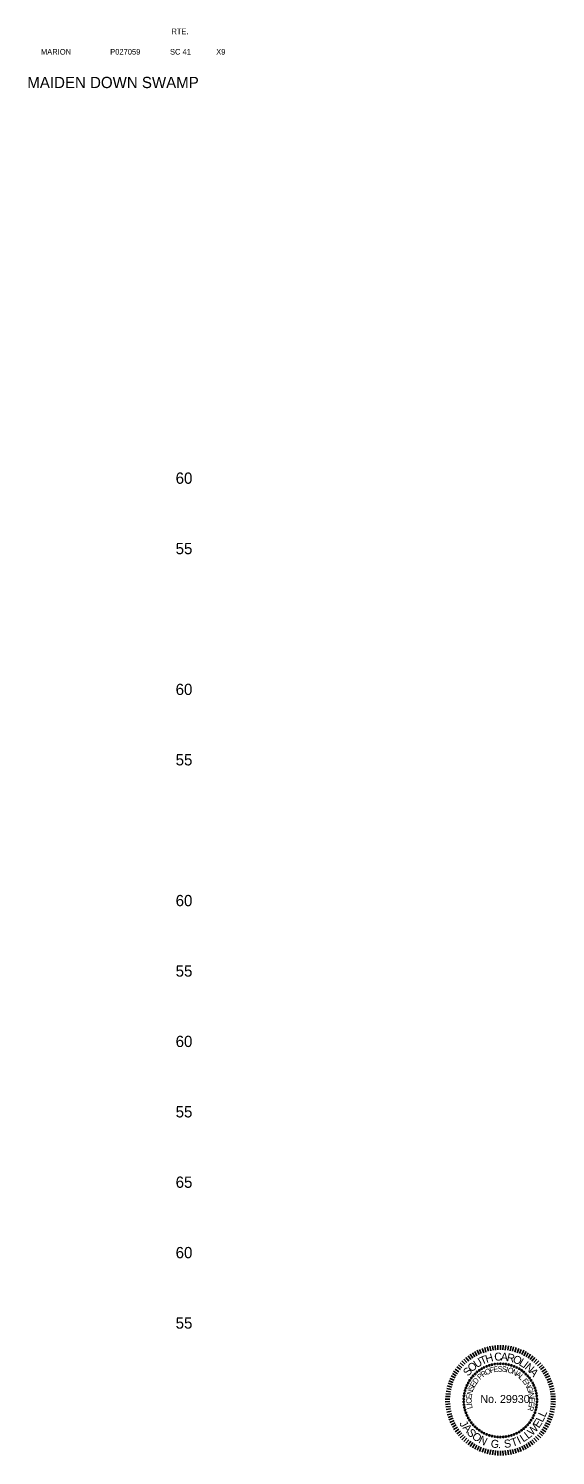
# Model space of a CAD drawing. Extents: x 1001 to 1184, y 1001 to 1447.
# Drawn here: x 1146.5 to 1183.9, y 1346 to 1447.3 of the extents above; entities that cross this region are included whole.
import ezdxf

# ---------------------------------------------------------------- set-up
doc = ezdxf.new("R2010")
doc.units = 0
for name, color, linetype in [('RD_HC_Cl', 7, 'Continuous'), ('RD_SHT_TX', 7, 'Continuous'), ('RD_TX_PEShield', 7, 'Continuous'), ('RD_XS_TX_Elev_EX', 7, 'Continuous')]:
    doc.layers.add(name, color=color, linetype=linetype)

# ---------------------------------------------------------------- blocks, each defined once
blk = doc.blocks.new('STILLWELL')
at = {"layer": 'RD_TX_PEShield'}
for p, q in [((-21.1, 28.1), (-23, 30.7)), ((-19.7, 29.1), (-21.5, 31.8)), ((-18.2, 30), (-19.9, 32.8)), ((-16.7, 30.8), (-18.2, 33.7)), ((-15.1, 31.6), (-16.5, 34.6)), ((-13.6, 32.3), (-14.8, 35.3)), ((-11.9, 32.9), (-13, 36)), ((-10.3, 33.4), (-11.2, 36.6)), ((-8.6, 33.9), (-9.4, 37.1)), ((-6.9, 34.3), (-7.5, 37.5)), ((-5.2, 34.6), (-5.7, 37.8)), ((-3.5, 34.8), (-3.8, 38)), ((-1.8, 34.9), (-1.9, 38.2)), ((0, 34.9), (0, 38.2)), ((1.7, 34.9), (1.9, 38.2)), ((3.4, 34.8), (3.7, 38)), ((5.2, 34.6), (5.6, 37.8)), ((6.9, 34.3), (7.5, 37.5)), ((8.6, 33.9), (9.3, 37.1)), ((10.2, 33.4), (11.2, 36.6)), ((11.9, 32.9), (13, 36)), ((13.5, 32.3), (14.7, 35.3)), ((15.1, 31.6), (16.5, 34.6)), ((16.6, 30.8), (18.2, 33.7)), ((18.2, 30), (19.8, 32.8)), ((19.6, 29.1), (21.4, 31.8)), ((21.1, 28.1), (23, 30.7)), ((-29.5, 19.4), (-32.2, 21.3)), ((-28.5, 20.9), (-31.1, 22.8)), ((-27.4, 22.2), (-29.9, 24.3)), ((-26.3, 23.5), (-28.7, 25.7)), ((-25.1, 24.7), (-27.4, 27.1)), ((-23.8, 25.9), (-26, 28.4)), ((-22.5, 27), (-24.5, 29.6)), ((22.4, 27), (24.5, 29.6)), ((23.8, 25.9), (25.9, 28.4)), ((25, 24.7), (27.3, 27.1)), ((26.2, 23.5), (28.6, 25.7)), ((27.4, 22.2), (29.9, 24.3)), ((28.5, 20.9), (31.1, 22.8)), ((29.5, 19.4), (32.2, 21.3)), ((-34.1, 10.2), (-37.2, 11.2)), ((-33.6, 11.8), (-36.6, 12.9)), ((-32.9, 13.4), (-35.9, 14.7)), ((-32.2, 15), (-35.1, 16.4)), ((-31.4, 16.5), (-34.2, 18.1)), ((-30.5, 18), (-33.3, 19.7)), ((30.4, 18), (33.2, 19.7)), ((31.3, 16.5), (34.2, 18.1)), ((32.1, 15), (35.1, 16.4)), ((32.9, 13.4), (35.9, 14.7)), ((33.5, 11.8), (36.6, 12.9)), ((34.1, 10.2), (37.2, 11.2)), ((-35.9, -0.1), (-39.2, 0)), ((-35.8, 1.7), (-39.1, 1.9)), ((-35.6, 3.4), (-38.9, 3.8)), ((-35.4, 5.1), (-38.6, 5.7)), ((-35.1, 6.8), (-38.2, 7.5)), ((-34.6, 8.5), (-37.8, 9.4)), ((34.6, 8.5), (37.7, 9.4)), ((35, 6.8), (38.2, 7.5)), ((35.3, 5.1), (38.5, 5.7)), ((35.6, 3.4), (38.8, 3.8)), ((35.7, 1.7), (39, 1.9)), ((35.8, -0.1), (39.1, 0)), ((-35.9, -1.8), (-39.2, -1.9)), ((-35.8, -3.5), (-39.1, -3.8)), ((-35.6, -5.3), (-38.9, -5.6)), ((-35.4, -7), (-38.6, -7.5)), ((-35.1, -8.7), (-38.2, -9.4)), ((35, -8.7), (38.2, -9.4)), ((35.3, -7), (38.5, -7.5)), ((35.6, -5.3), (38.8, -5.6)), ((35.7, -3.5), (39, -3.8)), ((35.8, -1.8), (39.1, -1.9)), ((-34.6, -10.4), (-37.8, -11.2)), ((-34.1, -12), (-37.2, -13)), ((-33.6, -13.6), (-36.6, -14.8)), ((-32.9, -15.3), (-35.9, -16.6)), ((-32.2, -16.8), (-35.1, -18.3)), ((-31.4, -18.4), (-34.2, -19.9)), ((-30.5, -19.9), (-33.3, -21.6)), ((30.4, -19.9), (33.2, -21.6)), ((31.3, -18.4), (34.2, -19.9)), ((32.1, -16.8), (35.1, -18.3)), ((32.9, -15.3), (35.9, -16.6)), ((33.5, -13.6), (36.6, -14.8)), ((34.1, -12), (37.2, -13)), ((34.6, -10.4), (37.7, -11.2)), ((-29.5, -21.3), (-32.2, -23.2)), ((-28.5, -22.7), (-31.1, -24.7)), ((-27.4, -24.1), (-29.9, -26.2)), ((-26.3, -25.4), (-28.7, -27.6)), ((-25.1, -26.6), (-27.4, -28.9)), ((-23.8, -27.8), (-26, -30.2)), ((-22.5, -28.9), (-24.5, -31.4)), ((-21.1, -29.9), (-23, -32.6)), ((21.1, -29.9), (23, -32.6)), ((22.4, -28.9), (24.5, -31.4)), ((23.8, -27.8), (25.9, -30.2)), ((25, -26.6), (27.3, -28.9)), ((26.2, -25.4), (28.6, -27.6)), ((27.4, -24.1), (29.9, -26.2)), ((28.5, -22.7), (31.1, -24.7)), ((29.5, -21.3), (32.2, -23.2)), ((-19.7, -30.9), (-21.5, -33.7)), ((-18.2, -31.8), (-19.9, -34.7)), ((-16.7, -32.7), (-18.2, -35.6)), ((-15.1, -33.5), (-16.5, -36.4)), ((-13.6, -34.1), (-14.8, -37.2)), ((-11.9, -34.8), (-13, -37.8)), ((-10.3, -35.3), (-11.2, -38.4)), ((-8.6, -35.8), (-9.4, -38.9)), ((-6.9, -36.1), (-7.5, -39.3)), ((-5.2, -36.4), (-5.7, -39.7)), ((-3.5, -36.6), (-3.8, -39.9)), ((-1.8, -36.8), (-1.9, -40)), ((0, -36.8), (0, -40.1)), ((1.7, -36.8), (1.9, -40)), ((3.4, -36.6), (3.7, -39.9)), ((5.2, -36.4), (5.6, -39.7)), ((6.9, -36.1), (7.5, -39.3)), ((8.6, -35.8), (9.3, -38.9)), ((10.2, -35.3), (11.2, -38.4)), ((11.9, -34.8), (13, -37.8)), ((13.5, -34.1), (14.7, -37.2)), ((15.1, -33.5), (16.5, -36.4)), ((16.6, -32.7), (18.2, -35.6)), ((18.2, -31.8), (19.8, -34.7)), ((19.6, -30.9), (21.4, -33.7))]:
    blk.add_line(p, q, dxfattribs=at)
for centre in [(-15, 20.4), (-13.3, 21.5), (-11.6, 22.4), (-9.8, 23.2), (-7.9, 23.9), (-6, 24.4), (-4, 24.8), (-2, 25), (0, 25.1), (2, 25), (3.9, 24.8), (5.9, 24.4), (7.8, 23.9), (9.7, 23.2), (11.5, 22.4), (13.3, 21.5), (15, 20.4), (-23.8, 9.7), (-22.9, 11.5), (-21.9, 13.2), (-20.7, 14.9), (-19.5, 16.4), (-18.1, 17.8), (-16.6, 19.2), (16.5, 19.2), (18, 17.8), (19.4, 16.4), (20.7, 14.9), (21.8, 13.2), (22.9, 11.5), (23.7, 9.7), (-26.1, 0.1), (-25.9, 2.1), (-25.6, 4), (-25.1, 6), (-24.5, 7.9), (24.5, 7.9), (25.1, 6), (25.5, 4), (25.8, 2.1), (26, 0.1), (-26.1, -1.9), (-25.9, -3.9), (-25.6, -5.9), (-25.1, -7.8), (-24.5, -9.7), (24.5, -9.7), (25.1, -7.8), (25.5, -5.9), (25.8, -3.9), (26, -1.9), (-23.8, -11.6), (-22.9, -13.4), (-21.9, -15.1), (-20.7, -16.7), (-19.5, -18.3), (-18.1, -19.7), (18, -19.7), (19.4, -18.3), (20.7, -16.7), (21.8, -15.1), (22.9, -13.4), (23.7, -11.6), (-16.6, -21), (-15, -22.2), (-13.3, -23.3), (-11.6, -24.3), (-9.8, -25.1), (-7.9, -25.8), (-6, -26.3), (-4, -26.7), (-2, -26.9), (0, -27), (2, -26.9), (3.9, -26.7), (5.9, -26.3), (7.8, -25.8), (9.7, -25.1), (11.5, -24.3), (13.3, -23.3), (15, -22.2), (16.5, -21)]:
    blk.add_circle(centre, 0.49, dxfattribs=at)
for s, height, rotation, p in [('T', 5.68, 23.5044, (-13.2, 24.1)), ('H', 5.68, 16.1357, (-9.9, 25.6)), ('C', 5.68, 4.076, (-4.2, 27.1)), ('A', 5.68, 355.3651, (0.1, 27.4)), ('R', 5.68, 347.3188, (4.1, 27.1)), ('O', 5.68, 338.6079, (8.3, 26.2)), ('S', 5.68, 49.6435, (-22.9, 15.8)), ('O', 5.68, 41.5972, (-20.4, 18.8)), ('U', 5.68, 32.2152, (-16.9, 21.8)), ('O', 3.92, 24.9735, (-10, 16.9)), ('F', 3.92, 15.9995, (-7.1, 18.3)), ('E', 3.92, 8.9511, (-4.7, 19)), ('S', 3.92, 1.2546, (-1.9, 19.4)), ('S', 3.92, 353.558, (0.8, 19.5)), ('I', 3.92, 345.8615, (3.5, 19.2)), ('O', 3.92, 342.6583, (4.7, 19)), ('N', 3.92, 333.6842, (7.7, 18)), ('L', 5.68, 329.226, (12.6, 24.4)), ('I', 5.68, 322.5218, (15.5, 22.8)), ('N', 5.68, 319.1729, (16.8, 21.8)), ('A', 5.68, 310.4621, (20.1, 19)), ('E', 3.92, 60.2341, (-18.5, 7.9)), ('D', 3.92, 52.5376, (-17.1, 10.3)), ('P', 3.92, 41.0022, (-14.5, 13.5)), ('R', 3.92, 33.3057, (-12.5, 15.3)), ('A', 3.92, 325.3521, (10.4, 16.7)), ('L', 3.92, 317.6555, (12.6, 15.1)), ('E', 3.92, 308.0396, (15.1, 12.8)), ('N', 3.92, 300.343, (16.8, 10.6)), ('C', 3.92, 92.2915, (-20.4, -3.2)), ('E', 3.92, 83.9594, (-20.5, -0.2)), ('N', 3.92, 76.2628, (-20.2, 2.5)), ('S', 3.92, 67.9307, (-19.5, 5.4)), ('G', 3.92, 292.0109, (18.3, 8.1)), ('I', 3.92, 283.0368, (19.5, 5.1)), ('N', 3.92, 279.8336, (19.8, 4)), ('E', 3.92, 271.5014, (20.3, 1.1)), ('I', 3.92, 95.4947, (-20.2, -4.3)), ('L', 3.92, 101.9075, (-19.7, -6.6)), ('R', 3.92, 256.1083, (20.1, -4.4)), ('E', 3.92, 263.8049, (20.4, -1.7)), ('L', 5.68, 65.098, (31.6, -13.3)), ('J', 5.68, 299.033, (-29.4, -17.3)), ('A', 5.68, 310.5887, (-27.2, -20.6)), ('W', 5.68, 47.0518, (22.6, -26.4)), ('E', 5.68, 56.4327, (27.3, -21.1)), ('L', 5.68, 65.098, (30, -16.9)), ('S', 5.68, 310.5887, (-24.3, -24)), ('O', 5.68, 321.0072, (-20.8, -27.4)), ('N', 5.68, 333.4326, (-16, -30.8)), ('G', 5.68, 352.2045, (-7.2, -34.2)), ('S', 5.68, 8.0826, (2.9, -34.8)), ('T', 5.68, 18.9019, (8.5, -33.9)), ('I', 5.68, 25.3991, (13.3, -32.2)), ('L', 5.68, 34.0644, (16.2, -30.9)), ('L', 5.68, 37.6708, (19.6, -28.7)), ('.', 5.68, 0.8698, (-1.8, -34.9))]:
    blk.add_text(s, height=height, rotation=rotation, dxfattribs=at).set_placement(p)
blk.add_text('No. 29930', height=5.68, dxfattribs=at).set_placement((-14.3, -2.8))

msp = doc.modelspace()

# ---------------------------------------------------------------- block references
at = {"layer": 'RD_HC_Cl', "xscale": 0.1, "yscale": 0.10000000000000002}
msp.add_blockref('STILLWELL', (1180, 1350), dxfattribs=at)

# ---------------------------------------------------------------- texts
at = {"layer": 'RD_SHT_TX'}
for s, height, p in [('RTE.', 0.4, (1156.62, 1446.93)), ('MARION', 0.4, (1147.35, 1445.48)), ('P027059', 0.4, (1152.27, 1445.48)), ('SC 41', 0.4, (1156.52, 1445.48)), ('X9', 0.4, (1159.8, 1445.48)), ('MAIDEN DOWN SWAMP', 0.8, (1146.38, 1443.1))]:
    msp.add_text(s, height=height, dxfattribs=at).set_placement(p)
at = {"layer": 'RD_XS_TX_Elev_EX'}
for s, p in [('60', (1156.92, 1415)), ('55', (1156.92, 1410)), ('60', (1156.92, 1400)), ('55', (1156.92, 1395)), ('60', (1156.92, 1385)), ('55', (1156.92, 1380)), ('60', (1156.92, 1375)), ('55', (1156.92, 1370)), ('65', (1156.92, 1365)), ('60', (1156.92, 1360)), ('55', (1156.92, 1355))]:
    msp.add_text(s, height=0.8, dxfattribs=at).set_placement(p)

doc.saveas('drawing.dxf')
